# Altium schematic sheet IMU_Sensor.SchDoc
size A4; SheetNumber: 3; SheetTotal: 4
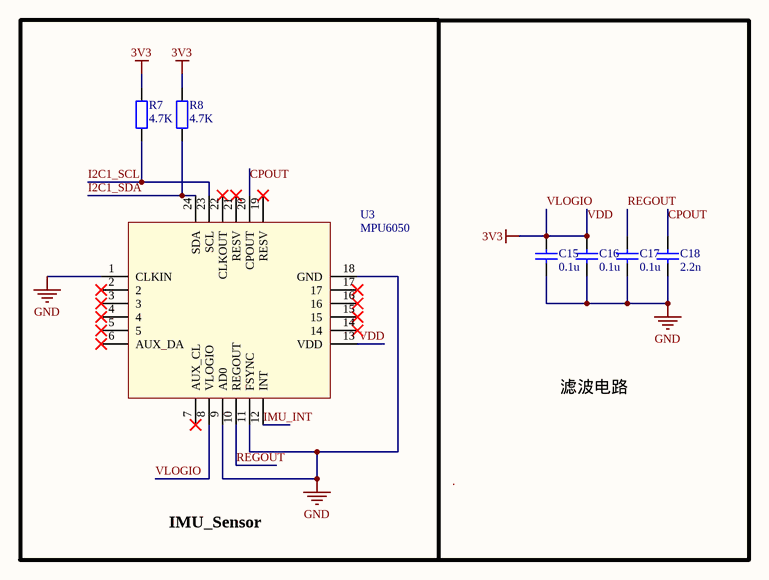
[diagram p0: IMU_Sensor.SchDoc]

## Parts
C15  0.1u  [C0402_M]
C16  0.1u  [C0402_M]
C17  0.1u  [C0402_M]
C18  2.2n  [C0402_M]
R7  4.7K  [R0402_M]
R8  4.7K  [R0402_M]
U3  MPU6050  [QFN-24_L4.0-W4.0-P0.50-BL-EP2.7]

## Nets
GND: C15.1 C16.1 C17.1 C18.1 U3.1(CLKIN) U3.9(AD0) U3.11(FSYNC) U3.18(GND)
VDD: C15.2 C16.2 R7.2 R8.2 U3.8(VLOGIO) U3.13(VDD)  [also labelled 3V3, VLOGIO]
CPOUT: C18.2 U3.20(CPOUT)
I2C1_SCL: R7.1 U3.23(SCL)
I2C1_SDA: R8.1 U3.24(SDA)
IMU_INT: U3.12(INT)
REGOUT: C17.2 U3.10(REGOUT)

Not connected (* = marked no-connect by the designer): U3 2* 3* 4* 5* 6(AUX_DA)* 7(AUX_CL)* 14* 15* 16* 17* 19(RESV)* 21(RESV)* 22(CLKOUT)*

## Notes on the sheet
- 滤波电路
- IMU_Sensor
- Labels drawn without touching a wire or pin: ·

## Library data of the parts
C15-C18 = C: 贴片电容/MLCC电容; BOM名称: 无极性贴片电容; 当前库版本V2022.12.25 @淘宝卖家:黄晶宝石: 最新版本发布https://shop463601444.taobao.com
R7 R8 = R: 贴片电阻; 联系下单店铺卖家 免费帮你查找封装: 联系下单店铺卖家 免费技术支持
U3 = MPU6050: 三轴加速度+三轴陀螺仪; 封装库来自淘宝卖家：黄晶宝石: 其他店铺购入均为盗版封装库，请立即申请退款，本店现金奖励100~500元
